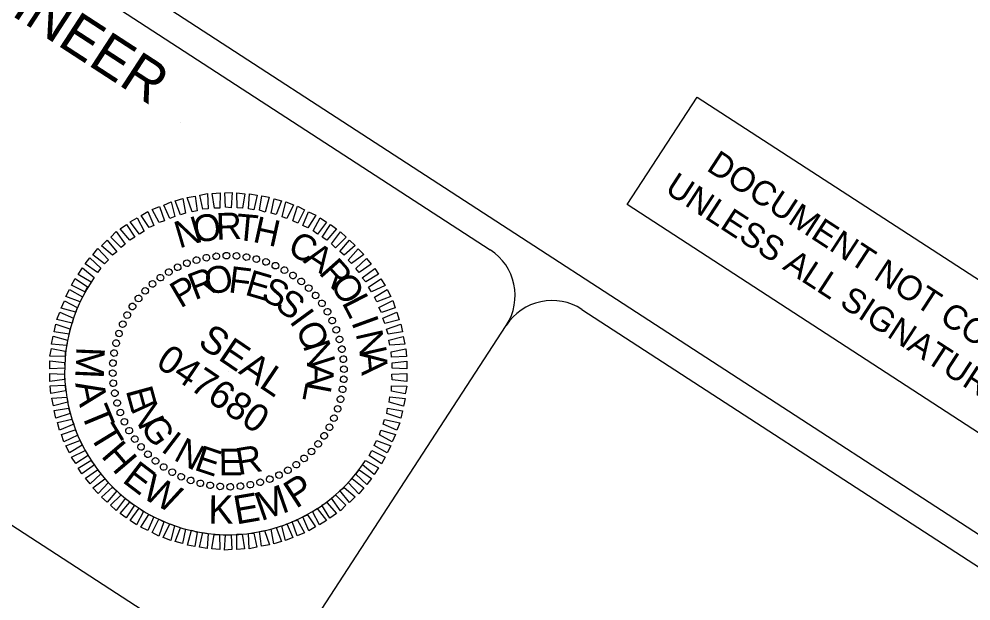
# Model space of a CAD drawing. Extents: x 2291197 to 2302790, y 592892 to 604246.
# Drawn here: x 2298859 to 2299556, y 597785 to 598211 of the extents above; entities that cross this region are included whole.
import ezdxf

# ---------------------------------------------------------------- set-up
doc = ezdxf.new("R2010")
doc.units = 0
for name, color, linetype in [('Old_Level_2', 7, 'Continuous'), ('Scratch_Level_0', 7, 'Continuous'), ('Sheet Sticker Exception Certification CELL', 7, 'Continuous'), ('Sheet Title CELL', 7, 'Continuous')]:
    doc.layers.add(name, color=color, linetype=linetype)

msp = doc.modelspace()

# ---------------------------------------------------------------- linework, layer by layer
at = {"layer": 'Old_Level_2'}
for p, q in [((2298977.5, 598135.4), (2298977.5, 598135.4)), ((2298989.01, 598034.53), (2298989.01, 598034.53)), ((2298996.11, 598036.16), (2298996.11, 598036.16)), ((2299003.54, 598037.37), (2299003.54, 598037.37)), ((2299010.79, 598037.68), (2299010.79, 598037.68)), ((2299018.28, 598037.44), (2299018.28, 598037.44)), ((2299025.64, 598036.69), (2299025.64, 598036.69)), ((2299032.77, 598035.27), (2299032.77, 598035.27)), ((2298975.13, 598029.27), (2298975.13, 598029.27)), ((2298981.98, 598032.06), (2298981.98, 598032.06)), ((2299039.82, 598033.11), (2299039.82, 598033.11)), ((2299046.78, 598030.19), (2299046.78, 598030.19)), ((2299053.41, 598027.08), (2299053.41, 598027.08)), ((2298962.49, 598021.58), (2298962.49, 598021.58)), ((2298968.71, 598025.59), (2298968.71, 598025.59)), ((2299059.73, 598023.18), (2299059.73, 598023.18)), ((2298956.64, 598016.93), (2298956.64, 598016.93)), ((2299065.68, 598018.71), (2299065.68, 598018.71)), ((2299071.12, 598013.76), (2299071.12, 598013.76)), ((2298946.56, 598006.38), (2298946.56, 598006.38)), ((2298951.51, 598011.82), (2298951.51, 598011.82)), ((2299076.23, 598008.63), (2299076.23, 598008.63)), ((2298942.09, 598000.43), (2298942.09, 598000.43)), ((2299080.89, 598002.78), (2299080.89, 598002.78)), ((2298938.18, 597994.11), (2298938.18, 597994.11)), ((2299084.89, 597996.56), (2299084.89, 597996.56)), ((2298935.08, 597987.47), (2298935.08, 597987.47)), ((2299088.57, 597990.14), (2299088.57, 597990.14)), ((2298932.16, 597980.51), (2298932.16, 597980.51)), ((2299091.36, 597983.29), (2299091.36, 597983.29)), ((2298930, 597973.47), (2298930, 597973.47)), ((2299093.83, 597976.25), (2299093.83, 597976.25)), ((2298928.58, 597966.33), (2298928.58, 597966.33)), ((2299095.46, 597969.16), (2299095.46, 597969.16)), ((2298927.83, 597958.98), (2298927.83, 597958.98)), ((2299096.67, 597961.73), (2299096.67, 597961.73)), ((2298927.58, 597951.49), (2298927.58, 597951.49)), ((2299012.29, 597952.98), (2299012.29, 597952.98)), ((2299096.99, 597954.48), (2299096.99, 597954.48)), ((2298927.9, 597944.23), (2298927.9, 597944.23)), ((2299096.75, 597946.99), (2299096.75, 597946.99)), ((2298929.11, 597936.81), (2298929.11, 597936.81)), ((2299095.99, 597939.63), (2299095.99, 597939.63)), ((2298930.74, 597929.71), (2298930.74, 597929.71)), ((2299094.57, 597932.5), (2299094.57, 597932.5)), ((2298933.21, 597922.67), (2298933.21, 597922.67)), ((2299092.41, 597925.45), (2299092.41, 597925.45)), ((2298936, 597915.82), (2298936, 597915.82)), ((2299089.49, 597918.49), (2299089.49, 597918.49)), ((2298939.68, 597909.41), (2298939.68, 597909.41)), ((2299086.39, 597911.86), (2299086.39, 597911.86)), ((2298943.68, 597903.18), (2298943.68, 597903.18)), ((2299082.48, 597905.54), (2299082.48, 597905.54)), ((2298948.34, 597897.34), (2298948.34, 597897.34)), ((2299078.01, 597899.59), (2299078.01, 597899.59)), ((2298953.45, 597892.2), (2298953.45, 597892.2)), ((2299067.93, 597889.03), (2299067.93, 597889.03)), ((2299073.07, 597894.15), (2299073.07, 597894.15)), ((2298958.89, 597887.26), (2298958.89, 597887.26)), ((2298964.84, 597882.79), (2298964.84, 597882.79)), ((2299062.09, 597884.38), (2299062.09, 597884.38)), ((2298971.16, 597878.88), (2298971.16, 597878.88)), ((2298977.8, 597875.77), (2298977.8, 597875.77)), ((2299042.6, 597873.9), (2299042.6, 597873.9)), ((2299049.44, 597876.7), (2299049.44, 597876.7)), ((2299055.86, 597880.38), (2299055.86, 597880.38)), ((2298984.76, 597872.86), (2298984.76, 597872.86)), ((2298991.8, 597870.69), (2298991.8, 597870.69)), ((2298998.93, 597869.28), (2298998.93, 597869.28)), ((2299006.29, 597868.52), (2299006.29, 597868.52)), ((2299013.78, 597868.28), (2299013.78, 597868.28)), ((2299021.03, 597868.6), (2299021.03, 597868.6)), ((2299028.46, 597869.81), (2299028.46, 597869.81)), ((2299035.56, 597871.43), (2299035.56, 597871.43))]:
    msp.add_line(p, q, dxfattribs=at)
for points in [[(2298993.59, 598071.61), (2298991.41, 598081.88), (2298997.02, 598083.07), (2298997.57, 598071.84)], [(2299002.1, 598072.31), (2299000.43, 598083.06), (2299006.19, 598083.55), (2299005.99, 598072.4)], [(2299010.24, 598073.06), (2299009.7, 598083.68), (2299015.12, 598083.98), (2299014.46, 598072.74)], [(2299018.76, 598072.55), (2299018.5, 598083.6), (2299024.35, 598083.01), (2299022.56, 598072.5)], [(2299027.06, 598071.99), (2299027.68, 598082.86), (2299033.35, 598081.99), (2299031, 598071.24)], [(2298969.52, 598064.91), (2298965.01, 598074.69), (2298970.36, 598077.05), (2298973.11, 598066.41)], [(2298977.26, 598067.53), (2298973.49, 598077.83), (2298978.99, 598079.49), (2298980.89, 598068.79)], [(2298985.71, 598069.69), (2298982.26, 598080.18), (2298987.91, 598081.14), (2298989.44, 598070.48)], [(2299035.21, 598070.92), (2299036.87, 598081.52), (2299042.22, 598080.45), (2299039.3, 598069.47)], [(2299043.62, 598068.67), (2299045.88, 598079.28), (2299051.09, 598077.7), (2299047.23, 598067.73)], [(2299051.6, 598066.1), (2299054.43, 598076.94), (2299059.88, 598074.81), (2299055.03, 598064.88)], [(2298954.25, 598058.14), (2298948.48, 598066.92), (2298953.45, 598069.92), (2298957.69, 598059.72)], [(2298961.6, 598062.01), (2298956.43, 598071.41), (2298961.84, 598073.53), (2298965.51, 598063.09)], [(2299059.41, 598063.24), (2299063.03, 598073.77), (2299067.97, 598071.16), (2299063.08, 598061.46)], [(2299066.75, 598059.68), (2299071.08, 598069.74), (2299076.26, 598067.18), (2299070.42, 598057.89)], [(2298947.18, 598053.47), (2298940.53, 598062.43), (2298945.5, 598065.43), (2298950.62, 598055.66)], [(2299074.28, 598055.78), (2299079.55, 598065.44), (2299084.13, 598062.26), (2299077.59, 598053.44)], [(2298933.77, 598043.67), (2298926.19, 598051.21), (2298930.22, 598055.24), (2298936.83, 598045.91)], [(2298940.31, 598049.08), (2298933.19, 598057.33), (2298937.88, 598060.52), (2298943.8, 598051.04)], [(2299080.98, 598051.23), (2299086.96, 598060.42), (2299091.54, 598057.25), (2299084.29, 598048.88)], [(2299087.78, 598046.2), (2299094.32, 598055.03), (2299098.44, 598051.15), (2299090.81, 598043.43)], [(2298927.52, 598038.08), (2298919.48, 598044.91), (2298923.6, 598049.08), (2298930.58, 598040.31)], [(2299093.84, 598040.66), (2299101, 598048.89), (2299105.2, 598045.14), (2299096.96, 598038.03)], [(2298921.69, 598031.6), (2298913.19, 598038.33), (2298916.88, 598042.77), (2298924.61, 598034.53)], [(2299100.04, 598034.41), (2299107.43, 598042.69), (2299111.51, 598038.43), (2299102.55, 598031.77)], [(2298916.57, 598025.26), (2298907.56, 598031.53), (2298910.88, 598036.01), (2298919.06, 598028.48)], [(2299105.64, 598028.16), (2299113.46, 598035.55), (2299116.93, 598031.28), (2299107.96, 598025.24)], [(2298911.83, 598018.28), (2298902.36, 598023.84), (2298905.49, 598028.65), (2298914.04, 598021.68)], [(2299110.35, 598021.47), (2299119.39, 598028.27), (2299122.25, 598024), (2299112.96, 598018.37)], [(2298907.38, 598011.12), (2298897.44, 598015.96), (2298900.29, 598020.96), (2298909.3, 598014.7)], [(2299114.97, 598014.64), (2299123.93, 598020.69), (2299127.03, 598015.86), (2299117.07, 598011.07)], [(2298903.81, 598003.77), (2298893.33, 598007.77), (2298896.03, 598012.86), (2298905.45, 598007.54)], [(2299119.36, 598007.16), (2299128.42, 598012.74), (2299131.1, 598007.58), (2299120.94, 598003.71)], [(2298900.67, 597996.15), (2298890.01, 597999.26), (2298892.29, 598004.62), (2298901.75, 597999.68)], [(2299122.39, 597999.75), (2299132.68, 598004.74), (2299134.43, 597999.38), (2299124.4, 597996.03)], [(2298897.95, 597988.26), (2298886.78, 597990.89), (2298888.97, 597996.11), (2298898.89, 597991.87)], [(2299125.43, 597991.74), (2299135.73, 597996.12), (2299137.38, 597990.61), (2299126.84, 597988.01)], [(2298895.8, 597980), (2298884.78, 597981.93), (2298886.07, 597987.33), (2298896.32, 597983.89)], [(2299127.96, 597983.86), (2299138.54, 597987.44), (2299139.73, 597981.84), (2299129.27, 597979.99)], [(2298894.02, 597971.69), (2298882.92, 597972.87), (2298884.02, 597978.6), (2298894.63, 597975.72)], [(2299129.83, 597975.59), (2299140.24, 597978.29), (2299141.43, 597972.69), (2299130.49, 597971.95)], [(2298892.9, 597963.77), (2298881.76, 597963.97), (2298882.77, 597969.55), (2298892.95, 597967.56)], [(2299131.48, 597967.28), (2299142.12, 597969.42), (2299142.61, 597963.67), (2299131.62, 597963.16)], [(2298892.53, 597955.15), (2298881.54, 597954.65), (2298881.61, 597960.64), (2298892.39, 597959.27)], [(2299132.13, 597959), (2299142.93, 597960.44), (2299142.95, 597954.59), (2299132.08, 597955.21)], [(2298892.44, 597946.96), (2298881.64, 597945.52), (2298881.62, 597951.37), (2298892.49, 597950.75)], [(2299132.04, 597950.81), (2299143.03, 597951.31), (2299142.96, 597945.32), (2299132.18, 597946.69)], [(2298893.1, 597938.68), (2298882.45, 597936.55), (2298881.96, 597942.3), (2298892.95, 597942.8)], [(2299131.67, 597942.2), (2299142.81, 597942), (2299141.8, 597936.42), (2299131.62, 597938.4)], [(2298894.74, 597930.37), (2298884.33, 597927.68), (2298883.14, 597933.28), (2298894.09, 597934.01)], [(2299130.55, 597934.27), (2299141.65, 597933.09), (2299140.55, 597927.37), (2299129.94, 597930.24)], [(2298896.61, 597922.11), (2298886.03, 597918.52), (2298884.84, 597924.12), (2298895.3, 597925.98)], [(2299128.77, 597925.97), (2299139.79, 597924.04), (2299138.5, 597918.64), (2299128.25, 597922.08)], [(2298899.14, 597914.23), (2298888.84, 597909.85), (2298887.19, 597915.35), (2298897.74, 597917.95)], [(2299126.62, 597917.7), (2299137.79, 597915.07), (2299135.6, 597909.85), (2299125.68, 597914.09)], [(2298902.18, 597906.21), (2298891.89, 597901.22), (2298890.14, 597906.59), (2298900.17, 597909.93)], [(2299123.9, 597909.81), (2299134.56, 597906.7), (2299132.29, 597901.34), (2299122.82, 597906.29)], [(2298905.21, 597898.8), (2298896.15, 597893.22), (2298893.47, 597898.39), (2298903.63, 597902.25)], [(2299120.76, 597902.19), (2299131.25, 597898.19), (2299128.54, 597893.11), (2299119.12, 597898.43)], [(2298909.61, 597891.32), (2298900.64, 597885.27), (2298897.54, 597890.1), (2298907.5, 597894.9)], [(2299117.2, 597894.85), (2299127.13, 597890), (2299124.28, 597885.01), (2299115.27, 597891.27)], [(2298914.23, 597884.49), (2298905.18, 597877.69), (2298902.32, 597881.97), (2298911.61, 597887.6)], [(2299112.74, 597887.68), (2299122.21, 597882.13), (2299119.08, 597877.32), (2299110.53, 597884.29)], [(2298918.94, 597877.81), (2298911.11, 597870.41), (2298907.65, 597874.68), (2298916.61, 597880.73)], [(2298924.53, 597871.55), (2298917.14, 597863.28), (2298913.06, 597867.53), (2298922.02, 597874.19)], [(2299102.88, 597874.37), (2299111.38, 597867.63), (2299107.69, 597863.19), (2299099.96, 597871.43)], [(2299108, 597880.7), (2299117.01, 597874.44), (2299113.69, 597869.95), (2299105.51, 597877.49)], [(2298930.74, 597865.31), (2298923.58, 597857.08), (2298919.37, 597860.82), (2298927.62, 597867.94)], [(2299097.05, 597867.89), (2299105.09, 597861.05), (2299100.97, 597856.89), (2299093.99, 597865.65)], [(2298936.79, 597859.76), (2298930.25, 597850.93), (2298926.13, 597854.81), (2298933.76, 597862.53)], [(2299090.8, 597862.29), (2299098.38, 597854.75), (2299094.35, 597850.73), (2299087.74, 597860.06)], [(2298943.59, 597854.74), (2298937.61, 597845.54), (2298933.03, 597848.72), (2298940.29, 597857.08)], [(2299084.26, 597856.88), (2299091.38, 597848.63), (2299086.69, 597845.44), (2299080.78, 597854.92)], [(2298950.29, 597850.18), (2298945.02, 597840.52), (2298940.44, 597843.7), (2298946.99, 597852.53)], [(2298957.82, 597846.29), (2298953.49, 597836.22), (2298948.31, 597838.78), (2298954.15, 597848.07)], [(2299070.33, 597847.83), (2299076.09, 597839.05), (2299071.12, 597836.04), (2299066.88, 597846.24)], [(2299077.39, 597852.49), (2299084.04, 597843.54), (2299079.07, 597840.53), (2299073.95, 597850.3)], [(2298965.17, 597842.72), (2298961.54, 597832.2), (2298956.6, 597834.81), (2298961.49, 597844.51)], [(2298972.97, 597839.86), (2298970.15, 597829.02), (2298964.69, 597831.16), (2298969.54, 597841.09)], [(2299055.05, 597841.05), (2299059.57, 597831.27), (2299054.21, 597828.92), (2299051.47, 597839.56)], [(2299062.98, 597843.95), (2299068.14, 597834.55), (2299062.74, 597832.43), (2299059.06, 597842.87)], [(2298980.96, 597837.29), (2298978.69, 597826.68), (2298973.48, 597828.26), (2298977.34, 597838.23)], [(2298989.36, 597835.05), (2298987.7, 597824.45), (2298982.36, 597825.51), (2298985.27, 597836.5)], [(2298997.52, 597833.97), (2298996.89, 597823.1), (2298991.22, 597823.97), (2298993.58, 597834.72)], [(2299005.81, 597833.41), (2299006.08, 597822.37), (2299000.22, 597822.96), (2299002.02, 597833.46)], [(2299014.33, 597832.9), (2299014.88, 597822.28), (2299009.45, 597821.99), (2299010.12, 597833.23)], [(2299022.47, 597833.65), (2299024.14, 597822.91), (2299018.39, 597822.42), (2299018.58, 597833.56)], [(2299030.98, 597834.36), (2299033.16, 597824.09), (2299027.55, 597822.9), (2299027, 597834.12)], [(2299038.87, 597836.28), (2299042.31, 597825.78), (2299036.66, 597824.83), (2299035.13, 597835.48)], [(2299047.31, 597838.43), (2299051.08, 597828.13), (2299045.58, 597826.48), (2299043.68, 597837.17)]]:
    msp.add_lwpolyline(points, close=True, dxfattribs=at)
for centre, major_axis in [((2298981.99, 598032.02), (-0.87, 2.27)), ((2298988.99, 598034.36), (-0.67, 2.34)), ((2298996.17, 598036.08), (-0.46, 2.39)), ((2299003.48, 598037.17), (-0.25, 2.42)), ((2299010.85, 598037.61), (-0.04, 2.43)), ((2299018.23, 598037.42), (0.17, 2.42)), ((2299025.57, 598036.58), (0.38, 2.4)), ((2299032.8, 598035.1), (0.59, 2.36)), ((2299039.88, 598033), (0.79, 2.3)), ((2298968.72, 598025.56), (-1.25, 2.08)), ((2298975.21, 598029.08), (-1.06, 2.18)), ((2299046.75, 598030.29), (0.99, 2.22)), ((2299053.36, 598027), (1.18, 2.12)), ((2298962.56, 598021.48), (-1.43, 1.97)), ((2299059.65, 598023.13), (1.36, 2.01)), ((2299065.58, 598018.74), (1.53, 1.89)), ((2298951.42, 598011.81), (-1.75, 1.69)), ((2298956.78, 598016.89), (-1.59, 1.83)), ((2299071.11, 598013.84), (1.69, 1.75)), ((2298946.53, 598006.28), (-1.89, 1.53)), ((2299076.19, 598008.48), (1.83, 1.59)), ((2298942.13, 598000.35), (-2.01, 1.36)), ((2299080.79, 598002.7), (1.97, 1.43)), ((2299084.86, 597996.54), (2.08, 1.25)), ((2298938.27, 597994.05), (-2.12, 1.18)), ((2299088.38, 597990.05), (2.18, 1.06)), ((2298934.97, 597987.45), (-2.22, 0.99)), ((2299091.32, 597983.28), (2.27, 0.87)), ((2298932.27, 597980.58), (-2.3, 0.79)), ((2299093.66, 597976.28), (2.34, 0.67)), ((2298930.16, 597973.5), (-2.36, 0.59)), ((2299095.38, 597969.09), (2.39, 0.46)), ((2298928.69, 597966.26), (-2.4, 0.38)), ((2298927.85, 597958.93), (-2.42, 0.17)), ((2299096.47, 597961.79), (2.42, 0.25)), ((2298927.65, 597951.54), (-2.43, -0.04)), ((2299096.92, 597954.42), (2.43, 0.04)), ((2298928.1, 597944.17), (-2.42, -0.25)), ((2299096.72, 597947.04), (2.42, -0.17)), ((2298929.19, 597936.87), (-2.39, -0.46)), ((2299095.88, 597939.7), (2.4, -0.38)), ((2298930.91, 597929.69), (-2.34, -0.67)), ((2299094.41, 597932.47), (2.36, -0.59)), ((2298933.25, 597922.68), (-2.27, -0.87)), ((2299092.31, 597925.39), (2.3, -0.79)), ((2298936.19, 597915.91), (-2.18, -1.06)), ((2299089.6, 597918.52), (2.22, -0.99)), ((2298939.71, 597909.42), (-2.08, -1.25)), ((2299086.3, 597911.91), (2.12, -1.18)), ((2298943.78, 597903.26), (-1.97, -1.43)), ((2299078.04, 597899.68), (1.89, -1.53)), ((2299082.44, 597905.62), (2.01, -1.36)), ((2298948.38, 597897.48), (-1.83, -1.59)), ((2298953.46, 597892.12), (-1.69, -1.75)), ((2299073.15, 597894.15), (1.75, -1.69)), ((2298958.99, 597887.22), (-1.53, -1.89)), ((2299067.79, 597889.07), (1.59, -1.83)), ((2298964.92, 597882.83), (-1.36, -2.01)), ((2298971.22, 597878.97), (-1.18, -2.12)), ((2299055.85, 597880.41), (1.25, -2.08)), ((2299062.01, 597884.48), (1.43, -1.97)), ((2298977.82, 597875.67), (-0.99, -2.22)), ((2298984.69, 597872.96), (-0.79, -2.3)), ((2299035.58, 597871.61), (0.67, -2.34)), ((2299042.58, 597873.95), (0.87, -2.27)), ((2299049.36, 597876.89), (1.06, -2.18)), ((2298991.77, 597870.86), (-0.59, -2.36)), ((2298999.01, 597869.39), (-0.38, -2.4)), ((2299006.34, 597868.55), (-0.17, -2.42)), ((2299013.72, 597868.35), (0.04, -2.43)), ((2299021.1, 597868.8), (0.25, -2.42)), ((2299028.4, 597869.88), (0.46, -2.39))]:
    msp.add_ellipse(centre, major_axis=major_axis, ratio=0.999708, dxfattribs=at)
at = {"layer": 'Scratch_Level_0'}
msp.add_arc((2299012.29, 597952.98), 119.81, 146.9737, 326.9737, dxfattribs=at)
at = {"layer": 'Sheet Sticker Exception Certification CELL'}
for p, q in [((2299304.14, 598075.01), (2299355.37, 598153.82)), ((2299355.37, 598153.82), (2299848.37, 597833.35)), ((2299797.13, 597754.54), (2299304.14, 598075.01))]:
    msp.add_line(p, q, dxfattribs=at)
at = {"layer": 'Sheet Title CELL'}
for p, q in [((2295040.33, 600772.38), (2299802.56, 597676.65)), ((2298534.03, 598477.41), (2299203.99, 598041.89)), ((2298301.32, 598199.42), (2299041.37, 597718.34)), ((2299271.07, 597998.29), (2299791.66, 597659.88)), ((2298866.91, 597449.97), (2299215.73, 597986.56))]:
    msp.add_line(p, q, dxfattribs=at)
for centre, start, end in [((2299182.19, 598008.36), 326.9737, 56.9737), ((2299249.27, 597964.75), 56.9737, 146.9737)]:
    msp.add_arc(centre, 40, start, end, dxfattribs=at)

# ---------------------------------------------------------------- texts
at = {"layer": 'Old_Level_2'}
for s, height, rotation, p in [('R', 19.56, 1.99421, (2299003.59, 598049.21)), ('N', 19.66, 16.3972, (2298976.28, 598042.81)), ('O', 19.64, 9.19544, (2298988.12, 598046.78)), ('T', 19.42, 354.79347, (2299017.26, 598049.18)), ('H', 19.27, 347.59318, (2299029.49, 598047.87)), ('C', 19.05, 333.19357, (2299054.67, 598039.55)), ('A', 19.03, 325.99402, (2299066.4, 598033.13)), ('R', 19.17, 311.5948, (2299077.92, 598024.84)), ('R', 19.63, 21.01335, (2298987.63, 598004.84)), ('O', 19.66, 11.65494, (2298997.09, 598008.55)), ('F', 19.38, 352.94073, (2299011.85, 598010.83)), ('P', 19.49, 30.37259, (2298977.21, 597998.73)), ('E', 19.2, 343.58477, (2299023.66, 598009.19)), ('S', 19.06, 334.22931, (2299035.36, 598005.81)), ('O', 19.31, 304.39486, (2299086.02, 598016.56)), ('S', 19.03, 324.8741, (2299045.64, 597999.33)), ('L', 19.46, 297.19458, (2299095.07, 598003.23)), ('I', 19.28, 306.1633, (2299056.52, 597989.44)), ('I', 19.58, 289.99384, (2299102.11, 597988.99)), ('SEAL', 20.245, 325.9737, (2298989.08, 597972.09)), ('O', 19.47, 296.80718, (2299060.89, 597983.78)), ('N', 19.66, 282.79261, (2299105.34, 597980.65)), ('047680', 20.251, 325.9737, (2298958.24, 597957.07)), ('N', 19.62, 287.45031, (2299066.69, 597971.96)), ('M', 20.81, 267.56825, (2298901.24, 597971.18)), ('A', 19.65, 275.59085, (2299108.26, 597966.87)), ('A', 19.58, 268.73397, (2299069.97, 597959.36)), ('A', 20.92, 281.38319, (2298900.11, 597944.14)), ('L', 19.39, 259.37455, (2299069.14, 597946.01)), ('E', 19.64, 285.25059, (2298937.09, 597938.86)), ('T', 20.79, 292.46021, (2298903.9, 597922.75)), ('N', 19.51, 294.60766, (2298940.61, 597925.71)), ('T', 20.61, 301.4602, (2298909.96, 597906.17)), ('G', 19.32, 303.96394, (2298947.23, 597912.35)), ('I', 19.04, 322.6749, (2298962.27, 597894.92)), ('H', 20.42, 310.46018, (2298918.55, 597890.74)), ('N', 19.04, 332.03009, (2298971.47, 597888.34)), ('E', 19.16, 341.38546, (2298986.58, 597880.93)), ('E', 19.52, 0.09779, (2299005.17, 597876.7)), ('R', 19.65, 9.45511, (2299019.53, 597876.82)), ('E', 20.26, 322.70161, (2298933.88, 597872.28)), ('W', 20.26, 332.0163, (2298947.97, 597860.65)), ('P', 20.67, 32.95592, (2299061.76, 597851.92)), ('M', 20.9, 19.14098, (2299036.19, 597843.03)), ('K', 20.75, 359.31574, (2298997.48, 597841.44)), ('E', 20.9, 9.82629, (2299018.08, 597840.61))]:
    msp.add_text(s, height=height, rotation=rotation, dxfattribs=at).set_placement(p)
at = {"layer": 'Sheet Sticker Exception Certification CELL'}
for s, p in [('DOCUMENT NOT CONSIDERED FINAL', (2299361.47, 598100.5)), ('UNLESS ALL SIGNATURES COMPLETED', (2299330.9, 598084.39))]:
    msp.add_text(s, height=18, rotation=326.9737, dxfattribs=at).set_placement(p)
at = {"layer": 'Sheet Title CELL'}
msp.add_text(' HYDRAULICS ENGINEER', height=30, rotation=326.9737, dxfattribs=at).set_placement((2298544.27, 598414.64))

doc.saveas('drawing.dxf')
